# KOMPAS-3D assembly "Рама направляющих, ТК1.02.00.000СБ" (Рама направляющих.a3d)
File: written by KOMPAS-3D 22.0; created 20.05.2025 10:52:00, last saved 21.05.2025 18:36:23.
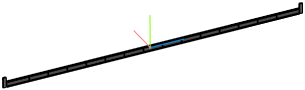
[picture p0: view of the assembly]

Document properties: Автор: TC; Полное имя файла: ТК1.02.00.000 СБ - Рама направляющих Сборочный чертеж.cdw

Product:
- Component [assembly]: Двутавр с ребрами  | designation ТК1.02.01.000СБ  | qty 1  | pos. 1  | Масса: 149.626885; Форматы листов документа: A4@4~3; source file: Двутавр с ребрами.a3d, ТК1.02.01.000 - Двутавр с ребрами.spw, ТК1.02.01.000 СБ - Двутавр с ребрами Сборочный чертеж.cdw
- Component [detail]: Труба$d100х50х4 ГОСТ 8645-68;09Г2 ГОСТ 13663-86$  | designation ТК1.02.00.001  | qty 2  | pos. 2
    Материал: Труба$d80х40х7 ГОСТ 8645-68;09Г2 ГОСТ 13663-86$ (density 7850 kg/m3)
    Масса: 2.076019
    Раздел спецификации: Детали
    Форматы листов документа: б/ч
    Примечание: m=2.07 кг / L=315 мм
    source file: Труба 100х50х4 ГОСТ 8645-68;09Г2 ГОСТ 13663-86$ — копия.m3d
- Component [standard]: Гайка М12-6H.04.019 ГОСТ 5915-70  | qty 2  | pos. 3  | Масса: 0.0184; Раздел спецификации: Стандартные изделия; Рассекать на разрезах: no
- Part/product: Рама направляющих  | designation ТК1.02.00.000СБ
    Масса: 153.815723
    Форматы листов документа: A3
    source file: ТК1.02.00.000 - Рама направляющих.spw

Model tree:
1. Эскиз:1  (with: Операция выдавливания:1)
2. Элемент выдавливания:1
     Расстояние 2 = 10
3. Эскиз:2  (with: Элемент выдавливания:1, Операция выдавливания:1, Элемент выдавливания:2)
     Ориентация = 2; Ориентация = 2; Ориентация = 2; Ориентация = 2

Referenced files in D:\Работа\2025\5. Май\Задание №6 - Тележка для крыши\3Д\Рама направляющих\: Двутавр с ребрами.a3d, Труба 100х50х4 ГОСТ 8645-68;09Г2 ГОСТ 13663-86$ — копия.m3d, ТК1.02.01.000 - Двутавр с ребрами.spw, ТК1.02.01.000 СБ - Двутавр с ребрами Сборочный чертеж.cdw
Referenced files in C:\Program Files\ASCON\KOMPAS-3D v22\Libs\PolynomLib\DATA\vault\Methods\Kompas\3D\: PLib_Nut_OST92_900.m3d
Referenced files in D:\Рабочая папка\АРХИВ\612\05\Задание №6 - Тележка для крыши\3Д\Рама направляющих\: Труба 100х50х4 ГОСТ 8645-68;09Г2 ГОСТ 13663-86$ — копия.m3d
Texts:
  ТК1.02.01.000
  ТК1.02.01.000 СБ
  ТК1.02.01.000       СБ
  ТК1.02.00.001
  BOSimple***SortamentEx:4194d098-baf7-48ce-a229-ad4525d580d6
  Крепежное изделие ГОСТ
  BOSimple***PART:f505569c-3e63-5d66-c876-e7484737b015***SHORTLOC:Root±30±10±20±©{}110±10±50±60[9;Цинковое, хроматированное;Сталь 10 ГОСТ 1050-2013;04;12;1,75;19]
  Точка начала. Х
  Точка начала. Y
  Точка начала. Z
  ТК1.02.00.000
  ТК1.02.00.000 СБ
  ТК1.02.01.000 Двутавр с ребрами
  ТК1.02.00.001 Труба100х50х4 ГОСТ 8645-68/09Г2 ГОСТ 13663-86 (1)
  ТК1.02.00.001 Труба100х50х4 ГОСТ 8645-68/09Г2 ГОСТ 13663-86 (2)
  Гайка М12-6H.04.019 ГОСТ 5915-70 (1)
  bcut1
  hole1
  hcut1
  hole2
  cut1
  Гайка М12-6H.04.019 ГОСТ 5915-70 (2)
